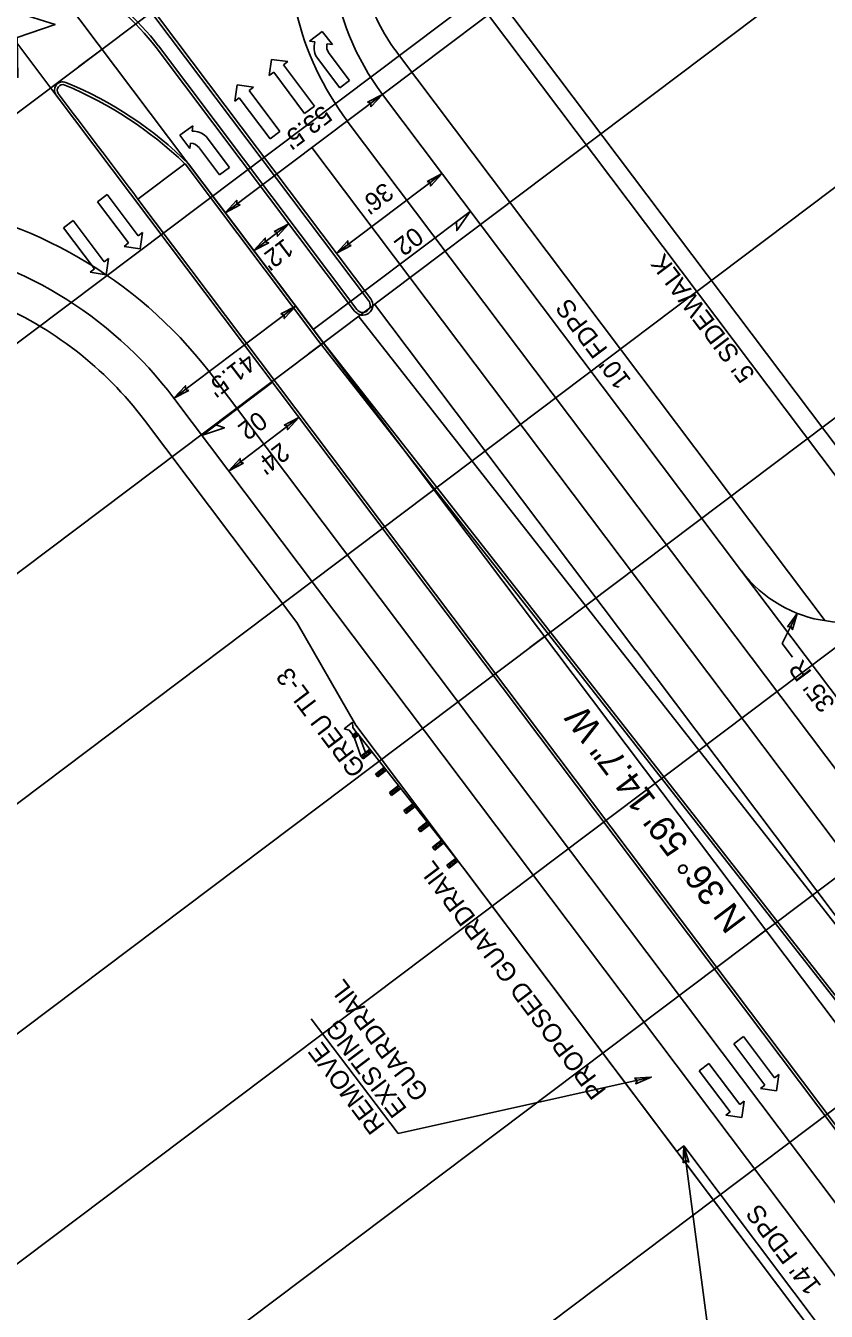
# Model space of a CAD drawing. Extents: x 1262309 to 1264352, y 775189 to 777755.
# Drawn here: x 1263383.2 to 1263600.9, y 776188.9 to 776538.6 of the extents above; entities that cross this region are included whole.
import ezdxf

# ---------------------------------------------------------------- set-up
doc = ezdxf.new("R2010")
doc.units = 0
for name, color, linetype in [('Default', 7, 'Continuous'), ('Prop Conc 1ft 6in Curb and Gutter', 7, 'Continuous'), ('Prop Conc 4in Sidewalk', 7, 'Continuous'), ('Prop Conc 5in Monolithic Keyed In Island', 7, 'Continuous'), ('Prop Conc Shoulder Berm Gutter', 7, 'Continuous'), ('Prop Dimension', 7, 'Continuous'), ('Prop Dimension Text', 7, 'Continuous'), ('Prop EOT', 7, 'Continuous'), ('Prop Guardrail', 7, 'Continuous'), ('Prop Guardrail Anchor Unit CELL', 7, 'Continuous'), ('Prop Horizontal Alignment', 7, 'Continuous'), ('Prop Horizontal Alignment Direction Label', 7, 'Continuous'), ('Prop Horizontal Alignment Tick Large', 7, 'Continuous'), ('Prop Horizontal Alignment Tick Small', 7, 'Continuous'), ('Prop Lane Arrow CELL', 7, 'Continuous'), ('Prop Lane Lines', 7, 'Continuous'), ('Prop Paved Shoulder', 7, 'Continuous'), ('Prop RDY Traffic Signal CELL', 7, 'Continuous'), ('Prop Superelevation  Arrow CELL', 7, 'Continuous'), ('Prop Superelevation Label', 7, 'Continuous'), ('Prop Terminator CELL', 7, 'Continuous'), ('Scratch_Level_3', 7, 'Continuous')]:
    doc.layers.add(name, color=color, linetype=linetype)

msp = doc.modelspace()

# ---------------------------------------------------------------- linework, layer by layer
at = {"layer": 'Default'}
for p, q in [((1263403.93, 776532.24), (1263403.93, 776532.24)), ((1263403.93, 776532.24), (1263403.93, 776532.24)), ((1263464.09, 776452.36), (1263464.09, 776452.36)), ((1263464.09, 776452.36), (1263464.09, 776452.36)), ((1263509.77, 776410.72), (1263509.77, 776410.72)), ((1263524.25, 776372.48), (1263524.25, 776372.48)), ((1263524.25, 776372.48), (1263524.25, 776372.48)), ((1263584.42, 776292.61), (1263584.42, 776292.61)), ((1263584.42, 776292.61), (1263584.42, 776292.61))]:
    msp.add_line(p, q, dxfattribs=at)
at = {"layer": 'Prop Conc 1ft 6in Curb and Gutter'}
for p, q in [((1263462.6, 776453.08), (1263426.49, 776501.03)), ((1263620.98, 776216.22), (1263413.7, 776491.42)), ((1263638.31, 776228.96), (1263462.6, 776453.08))]:
    msp.add_line(p, q, dxfattribs=at)
at = {"layer": 'Prop Conc 4in Sidewalk'}
for p, q in [((1263631.62, 776387.01), (1263511.75, 776546.15)), ((1263627.63, 776384), (1263508.98, 776541.52))]:
    msp.add_line(p, q, dxfattribs=at)
at = {"layer": 'Prop Conc 5in Monolithic Keyed In Island'}
for p, q in [((1263408.37, 776554.17), (1263476.42, 776463.84)), ((1263419.24, 776533.1), (1263473.22, 776461.43)), ((1263413.7, 776491.42), (1263426.47, 776501.06))]:
    msp.add_line(p, q, dxfattribs=at)
for centre, radius, start, end in [((1263368.91, 776495.2), 63, 36.9874, 86.8533), ((1263393.23, 776521.08), 1.5, 67.3967, 216.9075), ((1263353.13, 776424.77), 105.82, 46.1303, 67.3967), ((1272518.94, 783374.71), 11414.25, 216.907462, 217.08822), ((1263474.82, 776462.63), 2, 216.9874, 36.9874)]:
    msp.add_arc(centre, radius, start, end, dxfattribs=at)
at = {"layer": 'Prop Conc Shoulder Berm Gutter'}
msp.add_line((1263560.24, 776232.45), (1263699.52, 776047.54), dxfattribs=at)
at = {"layer": 'Prop Dimension'}
for p, q in [((1263552.6, 776574.48), (1263437.44, 776487.74)), ((1263456.61, 776462.29), (1263423.46, 776437.32)), ((1263593, 776378.77), (1263588.88, 776370.58)), ((1263591.68, 776366.87), (1263588.88, 776370.58))]:
    msp.add_line(p, q, dxfattribs=at)
msp.add_lwpolyline([(1263441.49, 776489.85), (1263437.44, 776487.74), (1263440.56, 776491.12), (1263440.58, 776490.13)], close=True, dxfattribs=at)
at = {"layer": 'Prop Dimension Text'}
for p, q in [((1263467.65, 776476.72), (1263496.4, 776498.38)), ((1263454.74, 776484.72), (1263445.19, 776477.46)), ((1263457.46, 776432.07), (1263447.91, 776424.81)), ((1263447.91, 776424.81), (1263438.36, 776417.54)), ((1263484.43, 776237.3), (1263460.75, 776268.5)), ((1263484.43, 776237.3), (1263553.29, 776252.63)), ((1263573.35, 776148.51), (1263562.13, 776233.92))]:
    msp.add_line(p, q, dxfattribs=at)
for points in [[(1263476.12, 776517.82), (1263480.17, 776519.93), (1263477.06, 776516.55), (1263477.03, 776517.54)], [(1263492.35, 776496.27), (1263496.4, 776498.38), (1263493.29, 776495.01), (1263493.26, 776495.99)], [(1263450.69, 776482.61), (1263454.74, 776484.72), (1263451.62, 776481.35), (1263451.59, 776482.33)], [(1263449.24, 776479.56), (1263445.19, 776477.46), (1263448.3, 776480.83), (1263448.33, 776479.85)], [(1263471.7, 776478.83), (1263467.65, 776476.72), (1263470.76, 776480.1), (1263470.79, 776479.11)], [(1263453.41, 776429.96), (1263457.46, 776432.07), (1263454.34, 776428.7), (1263454.32, 776429.68)], [(1263442.41, 776419.65), (1263438.36, 776417.54), (1263441.48, 776420.92), (1263441.5, 776419.93)]]:
    msp.add_lwpolyline(points, close=True, dxfattribs=at)
at = {"layer": 'Prop EOT'}
for p, q in [((1263408.87, 776554.75), (1263477.01, 776464.29)), ((1263418.64, 776532.65), (1263472.62, 776460.98)), ((1263620.38, 776215.77), (1263391.43, 776519.73)), ((1263577.82, 776390.28), (1263480.17, 776519.93)), ((1263577.82, 776390.28), (1263480.18, 776519.91)), ((1263464.15, 776452.33), (1263427.44, 776501.01)), ((1263638.9, 776229.42), (1263464.15, 776452.33)), ((1263710.7, 776055.96), (1263423.46, 776437.32))]:
    msp.add_line(p, q, dxfattribs=at)
for centre, radius, start, end in [((1263368.91, 776495.2), 62.25, 36.9874, 86.8533), ((1263536.09, 776562.04), 70, 187.1062, 216.9874), ((1263393.23, 776521.08), 2.25, 67.3967, 216.9075), ((1263356.26, 776430.02), 100.53, 44.9264, 67.8935), ((1263335.56, 776371.06), 110.08, 37.0099, 81.1734), ((1263474.82, 776462.63), 2.75, 216.9874, 36.9874), ((1263605.77, 776411.36), 35, 216.9874, 306.9874)]:
    msp.add_arc(centre, radius, start, end, dxfattribs=at)
at = {"layer": 'Prop Guardrail'}
msp.add_line((1263502.31, 776309.36), (1263699.52, 776047.54), dxfattribs=at)
at = {"layer": 'Prop Guardrail Anchor Unit CELL'}
for p, q in [((1263472.07, 776349.18), (1263469.73, 776347.41)), ((1263469.73, 776347.41), (1263471.12, 776346.98)), ((1263471.12, 776346.98), (1263472.36, 776345.35)), ((1263473.1, 776346.5), (1263471.92, 776345.58)), ((1263472.1, 776347.72), (1263472.07, 776349.18)), ((1263473.33, 776346.09), (1263472.1, 776347.72)), ((1263473.1, 776346.5), (1263472.54, 776344.79)), ((1263472.84, 776345.72), (1263473.33, 776346.09)), ((1263502.28, 776309.34), (1263473.41, 776346.11)), ((1263471.92, 776345.58), (1263473.72, 776345.72)), ((1263472.54, 776344.79), (1263471.92, 776345.58)), ((1263472.54, 776344.79), (1263472.23, 776345.18)), ((1263472.36, 776345.35), (1263472.84, 776345.72)), ((1263473.72, 776345.72), (1263472.54, 776344.79)), ((1263474.34, 776339.97), (1263472.54, 776344.79)), ((1263475.54, 776340.92), (1263473.72, 776345.72)), ((1263476.75, 776341.86), (1263474.34, 776339.97)), ((1263474.34, 776339.97), (1263476.16, 776340.13)), ((1263474.95, 776339.18), (1263474.34, 776339.97)), ((1263477.36, 776341.07), (1263474.95, 776339.18)), ((1263475.54, 776340.92), (1263474.95, 776339.18)), ((1263477.36, 776341.07), (1263475.54, 776340.92)), ((1263476.16, 776340.13), (1263475.54, 776340.92)), ((1263476.16, 776340.13), (1263476.75, 776341.86)), ((1263480.64, 776336.91), (1263478.28, 776335.05)), ((1263481.25, 776336.12), (1263478.89, 776334.27)), ((1263479.46, 776335.98), (1263478.89, 776334.27)), ((1263481.25, 776336.12), (1263479.46, 776335.98)), ((1263480.07, 776335.19), (1263479.46, 776335.98)), ((1263480.07, 776335.19), (1263480.64, 776336.91)), ((1263478.28, 776335.05), (1263480.07, 776335.19)), ((1263478.89, 776334.27), (1263478.28, 776335.05)), ((1263484.53, 776331.95), (1263482.06, 776330.01)), ((1263482.06, 776330.01), (1263483.91, 776330.19)), ((1263482.68, 776329.22), (1263482.06, 776330.01)), ((1263485.14, 776331.16), (1263482.68, 776329.22)), ((1263483.29, 776330.98), (1263482.68, 776329.22)), ((1263485.14, 776331.16), (1263483.29, 776330.98)), ((1263483.91, 776330.19), (1263483.29, 776330.98)), ((1263483.91, 776330.19), (1263484.53, 776331.95)), ((1263488.42, 776326.99), (1263486.03, 776325.12)), ((1263486.03, 776325.12), (1263487.84, 776325.27)), ((1263486.65, 776324.33), (1263486.03, 776325.12)), ((1263489.04, 776326.21), (1263486.65, 776324.33)), ((1263487.22, 776326.06), (1263486.65, 776324.33)), ((1263489.04, 776326.21), (1263487.22, 776326.06)), ((1263487.84, 776325.27), (1263487.22, 776326.06)), ((1263487.84, 776325.27), (1263488.42, 776326.99)), ((1263489.04, 776326.21), (1263488.42, 776326.99)), ((1263492.31, 776322.04), (1263489.91, 776320.15)), ((1263491.73, 776320.31), (1263492.31, 776322.04)), ((1263489.91, 776320.15), (1263491.73, 776320.31)), ((1263490.53, 776319.37), (1263489.91, 776320.15)), ((1263492.93, 776321.25), (1263490.53, 776319.37)), ((1263491.11, 776321.09), (1263490.53, 776319.37)), ((1263492.93, 776321.25), (1263491.11, 776321.09)), ((1263491.73, 776320.31), (1263491.11, 776321.09)), ((1263496.2, 776317.08), (1263493.8, 776315.19)), ((1263493.8, 776315.19), (1263495.62, 776315.35)), ((1263494.42, 776314.41), (1263493.8, 776315.19)), ((1263496.82, 776316.29), (1263494.42, 776314.41)), ((1263495, 776316.14), (1263494.42, 776314.41)), ((1263496.82, 776316.29), (1263495, 776316.14)), ((1263495.62, 776315.35), (1263495, 776316.14)), ((1263495.62, 776315.35), (1263496.2, 776317.08)), ((1263500.09, 776312.12), (1263497.73, 776310.27)), ((1263500.71, 776311.34), (1263498.35, 776309.48)), ((1263498.91, 776311.2), (1263498.35, 776309.48)), ((1263500.09, 776312.12), (1263498.91, 776311.2)), ((1263498.91, 776311.2), (1263500.71, 776311.34)), ((1263499.53, 776310.41), (1263498.91, 776311.2)), ((1263499.53, 776310.41), (1263500.09, 776312.12)), ((1263500.71, 776311.34), (1263500.09, 776312.12)), ((1263497.73, 776310.27), (1263499.53, 776310.41)), ((1263498.35, 776309.48), (1263497.73, 776310.27))]:
    msp.add_line(p, q, dxfattribs=at)
at = {"layer": 'Prop Horizontal Alignment'}
msp.add_line((1263830.93, 775965.32), (1263334.24, 776624.75), dxfattribs=at)
at = {"layer": 'Prop Horizontal Alignment Tick Large'}
msp.add_line((1263403.93, 776532.24), (1263397.53, 776527.42), dxfattribs=at)
at = {"layer": 'Prop Horizontal Alignment Tick Small'}
for p, q in [((1263464.09, 776452.36), (1263460.1, 776449.35)), ((1263524.25, 776372.48), (1263520.26, 776369.47)), ((1263584.42, 776292.61), (1263580.42, 776289.6))]:
    msp.add_line(p, q, dxfattribs=at)
at = {"layer": 'Prop Lane Arrow CELL'}
for p, q in [((1263460.35, 776534.39), (1263463.83, 776537.08)), ((1263463.83, 776537.08), (1263466.58, 776533.51)), ((1263461.82, 776534.19), (1263460.35, 776534.39)), ((1263466.58, 776533.51), (1263465.11, 776533.72)), ((1263449.4, 776525.06), (1263449.98, 776529.44)), ((1263449.98, 776529.44), (1263454.44, 776528.85)), ((1263454.44, 776528.85), (1263453.24, 776527.94)), ((1263453.24, 776527.94), (1263461.66, 776516.76)), ((1263468.56, 776521.74), (1263462.22, 776530.17)), ((1263465.69, 776531.03), (1263471.2, 776523.72)), ((1263450.6, 776525.96), (1263449.4, 776525.06)), ((1263459.02, 776514.77), (1263450.6, 776525.96)), ((1263440.06, 776518.12), (1263440.64, 776522.5)), ((1263440.64, 776522.5), (1263445.09, 776521.91)), ((1263445.09, 776521.91), (1263443.89, 776521)), ((1263443.89, 776521), (1263452.31, 776509.82)), ((1263471.2, 776523.72), (1263468.56, 776521.74)), ((1263441.26, 776519.02), (1263440.06, 776518.12)), ((1263449.68, 776507.84), (1263441.26, 776519.02)), ((1263461.66, 776516.76), (1263459.02, 776514.77)), ((1263428.65, 776511.41), (1263425.11, 776508.8)), ((1263428.45, 776509.94), (1263428.65, 776511.41)), ((1263425.11, 776508.8), (1263427.78, 776505.18)), ((1263438.55, 776500.02), (1263432.2, 776508.45)), ((1263452.31, 776509.82), (1263449.68, 776507.84)), ((1263427.78, 776505.18), (1263427.98, 776506.65)), ((1263430.41, 776505.34), (1263435.91, 776498.03)), ((1263435.91, 776498.03), (1263438.55, 776500.02)), ((1263405.35, 776492.67), (1263402.71, 776490.69)), ((1263402.71, 776490.69), (1263411.13, 776479.51)), ((1263413.77, 776481.49), (1263405.35, 776492.67)), ((1263396.1, 776485.61), (1263393.46, 776483.62)), ((1263393.46, 776483.62), (1263401.88, 776472.44)), ((1263404.52, 776474.42), (1263396.1, 776485.61)), ((1263414.97, 776482.39), (1263413.77, 776481.49)), ((1263414.31, 776477.95), (1263414.97, 776482.39)), ((1263411.13, 776479.51), (1263409.94, 776478.6)), ((1263409.94, 776478.6), (1263414.31, 776477.95)), ((1263401.88, 776472.44), (1263400.69, 776471.54)), ((1263405.72, 776475.33), (1263404.52, 776474.42)), ((1263405.06, 776470.89), (1263405.72, 776475.33)), ((1263400.69, 776471.54), (1263405.06, 776470.89)), ((1263578.36, 776263.64), (1263575.73, 776261.66)), ((1263586.79, 776252.46), (1263578.36, 776263.64)), ((1263575.73, 776261.66), (1263584.15, 776250.47)), ((1263568.95, 776256.37), (1263566.31, 776254.39)), ((1263577.37, 776245.19), (1263568.95, 776256.37)), ((1263566.31, 776254.39), (1263574.74, 776243.21)), ((1263587.98, 776253.36), (1263586.79, 776252.46)), ((1263587.32, 776248.92), (1263587.98, 776253.36)), ((1263584.15, 776250.47), (1263582.95, 776249.57)), ((1263582.95, 776249.57), (1263587.32, 776248.92)), ((1263578.57, 776246.09), (1263577.37, 776245.19)), ((1263577.91, 776241.65), (1263578.57, 776246.09)), ((1263574.74, 776243.21), (1263573.54, 776242.3)), ((1263573.54, 776242.3), (1263577.91, 776241.65))]:
    msp.add_line(p, q, dxfattribs=at)
for centre, radius, start, end in [((1263466.83, 776532.65), 5.25, 162.9996, 208.3113), ((1263468.29, 776533), 3.27, 167.3292, 216.9874), ((1263428.54, 776504.7), 5.25, 45.6635, 90.9752), ((1263427.8, 776503.39), 3.27, 36.9874, 86.6456)]:
    msp.add_arc(centre, radius, start, end, dxfattribs=at)
at = {"layer": 'Prop Lane Lines'}
for p, q in [((1263392.17, 776518.75), (1263357.3, 776565.05)), ((1263568.24, 776383.06), (1263470.6, 776512.69)), ((1263558.65, 776375.84), (1263461.01, 776505.47)), ((1263549.07, 776368.62), (1263478.06, 776462.9)), ((1263648.34, 776236.82), (1263473.59, 776459.73)), ((1263794, 775965.32), (1263433.04, 776444.54)), ((1263636.77, 776312.02), (1263577.82, 776390.28)), ((1263685.9, 776226.85), (1263568.24, 776383.06)), ((1263676.32, 776219.63), (1263558.65, 776375.84)), ((1263648.34, 776236.82), (1263549.06, 776368.64))]:
    msp.add_line(p, q, dxfattribs=at)
for centre, radius, start, end in [((1263535.98, 776561.36), 81.5, 124.947, 216.6462), ((1263336.03, 776369.27), 122.79, 37.8117, 124.9498)]:
    msp.add_arc(centre, radius, start, end, dxfattribs=at)
at = {"layer": 'Prop Paved Shoulder'}
for p, q in [((1263600.54, 776376.75), (1263484.55, 776530.74)), ((1263456.88, 776376.33), (1263415.47, 776431.31)), ((1263472.94, 776348.36), (1263456.88, 776376.33)), ((1263560.24, 776232.45), (1263472.94, 776348.36)), ((1263562.13, 776233.92), (1263560.24, 776232.45)), ((1263795.48, 775924.14), (1263562.13, 776233.92))]:
    msp.add_line(p, q, dxfattribs=at)
for centre, radius, start, end in [((1263532.48, 776566.84), 60, 199.6151, 216.9874), ((1263335.59, 776371.14), 100, 36.9874, 67.456)]:
    msp.add_arc(centre, radius, start, end, dxfattribs=at)
at = {"layer": 'Prop RDY Traffic Signal CELL'}
msp.add_lwpolyline([(1263374.48, 776533.24), (1263381.03, 776524.55), (1263380.84, 776535.43), (1263391.15, 776538.98), (1263380.72, 776542.17), (1263380.53, 776553.06), (1263374.28, 776544.14), (1263363.87, 776547.32), (1263370.42, 776538.63), (1263364.17, 776529.69), (1263374.48, 776533.24)], dxfattribs=at)
at = {"layer": 'Prop Superelevation  Arrow CELL'}
for p, q in [((1263503.99, 776488.08), (1263461.36, 776455.98)), ((1263431.21, 776427.24), (1263450.26, 776441.63))]:
    msp.add_line(p, q, dxfattribs=at)
for points in [[(1263503.99, 776488.08), (1263500.4, 776482.88), (1263500.29, 776485.3)], [(1263431.21, 776427.24), (1263437.2, 776429.26), (1263434.9, 776430.02)]]:
    msp.add_lwpolyline(points, close=True, dxfattribs=at)
at = {"layer": 'Prop Terminator CELL'}
for points in [[(1263452.55, 776460.2), (1263456.61, 776462.29), (1263453.47, 776458.93), (1263453.45, 776459.92)], [(1263427.52, 776439.41), (1263423.46, 776437.32), (1263426.59, 776440.69), (1263426.61, 776439.7)], [(1263590.29, 776375.1), (1263593, 776378.77), (1263591.68, 776374.37), (1263591.22, 776375.24)], [(1263548.73, 776252.39), (1263553.29, 776252.65), (1263549.06, 776250.85), (1263549.44, 776251.76)], [(1263561.96, 776229.36), (1263562.13, 776233.92), (1263563.53, 776229.54), (1263562.66, 776230)]]:
    msp.add_lwpolyline(points, close=True, dxfattribs=at)
at = {"layer": 'Scratch_Level_3'}
for p, q in [((1263205.99, 776383.15), (1263701.09, 776756.06)), ((1263236.07, 776343.21), (1263731.17, 776716.12)), ((1263266.15, 776303.27), (1263761.25, 776676.19)), ((1263296.23, 776263.33), (1263791.33, 776636.25)), ((1263326.32, 776223.39), (1263821.42, 776596.31)), ((1263356.4, 776183.46), (1263851.5, 776556.37)), ((1263386.48, 776143.52), (1263881.58, 776516.43)), ((1263416.56, 776103.58), (1263911.66, 776476.49))]:
    msp.add_line(p, q, dxfattribs=at)

# ---------------------------------------------------------------- texts
at = {"layer": 'Prop Dimension'}
msp.add_text("35' R", height=5, rotation=127.0213, dxfattribs=at).set_placement((1263603.5, 776354.29))
at = {"layer": 'Prop Dimension Text'}
for s, rotation, p in [("53.5'", 217.2584, (1263463.97, 776517.24)), ("36'", 217.2584, (1263480.72, 776496.26)), ("12'", 217.2584, (1263453.55, 776480.98)), ("5' SIDEWALK", 127.0213, (1263581.68, 776443.89)), ("10' FDPS", 126.9874, (1263548, 776442.13)), ("41.5'", 217.2584, (1263443.38, 776449.83)), ("24'", 217.2584, (1263452.46, 776425.47)), ('GUARDRAIL', 126.9874, (1263493.05, 776248.49)), ('EXISTING', 126.9874, (1263487.06, 776243.98)), ('REMOVE', 126.9874, (1263481.06, 776239.47)), ("14' FDPS", 126.9874, (1263599.74, 776195.8))]:
    msp.add_text(s, height=5, rotation=rotation, dxfattribs=at).set_placement(p)
at = {"layer": 'Prop Guardrail'}
msp.add_text('PROPOSED GUARDRAIL', height=5, rotation=126.9874, dxfattribs=at).set_placement((1263541.27, 776248.98))
at = {"layer": 'Prop Guardrail Anchor Unit CELL'}
msp.add_text('GREU TL-3', height=5, rotation=126.9874, dxfattribs=at).set_placement((1263475.9, 776336.59))
at = {"layer": 'Prop Horizontal Alignment Direction Label'}
msp.add_text('N 36%%d 59\' 14.7" W', height=7, rotation=126.9874, dxfattribs=at).set_placement((1263579.43, 776295.32))
at = {"layer": 'Prop Superelevation Label'}
for rotation, p in [(216.9874, (1263488.85, 776484.15)), (217.0553, (1263446.38, 776434.04))]:
    msp.add_text('02', height=5, rotation=rotation, dxfattribs=at).set_placement(p)

doc.saveas('drawing.dxf')
